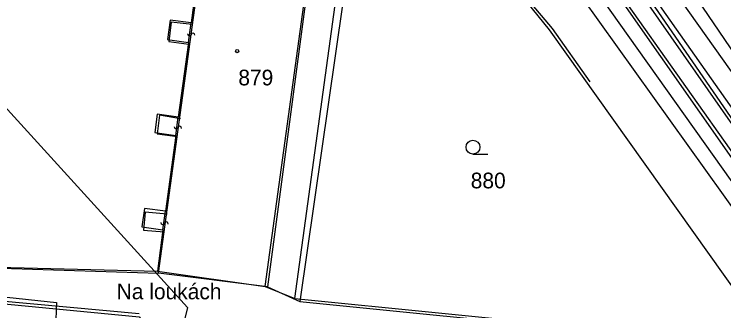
# Model space of a CAD drawing. Extents: x -469926 to -462499, y -1098642 to -1092733.
# Drawn here: x -465706.3 to -465629.3, y -1094774 to -1094741.9 of the extents above; entities that cross this region are included whole.
import ezdxf

# ---------------------------------------------------------------- set-up
doc = ezdxf.new("R2010")
doc.units = 0
for name, color, linetype in [('Vrstva 1', 7, 'Continuous'), ('Vrstva 10', 7, 'Continuous'), ('Vrstva 14', 7, 'Continuous'), ('Vrstva 16', 7, 'Continuous'), ('Vrstva 25', 7, 'Continuous'), ('Vrstva 4', 7, 'Continuous'), ('Vrstva 50', 7, 'Continuous'), ('Vrstva 6', 7, 'Continuous'), ('Vrstva 63', 7, 'Continuous')]:
    doc.layers.add(name, color=color, linetype=linetype)

msp = doc.modelspace()

# ---------------------------------------------------------------- linework, layer by layer
at = {"layer": 'Vrstva 1'}
for p, q in [((-465620.33, -1094764.94), (-465670.79, -1094691.66)), ((-465654.05, -1094726.95), (-465624.69, -1094768.01)), ((-465679.05, -1094771.4), (-465673.34, -1094729.79)), ((-465679.05, -1094771.4), (-465673.34, -1094729.79)), ((-465685.98, -1094734.61), (-465687.1, -1094742.81)), ((-465685.98, -1094734.61), (-465687.1, -1094742.81)), ((-465675.83, -1094772.71), (-465670.77, -1094735.7)), ((-465675.83, -1094772.71), (-465670.77, -1094735.7)), ((-465648.19, -1094743.56), (-465650.65, -1094740.51)), ((-465648.19, -1094743.56), (-465650.65, -1094740.51)), ((-465689.38, -1094742.5), (-465689.66, -1094744.62)), ((-465689.38, -1094742.5), (-465689.66, -1094744.62)), ((-465687.1, -1094742.81), (-465689.38, -1094742.5)), ((-465687.1, -1094742.81), (-465689.38, -1094742.5)), ((-465625.25, -1094775.81), (-465648.19, -1094743.56)), ((-465689.66, -1094744.62), (-465687.38, -1094744.93)), ((-465689.66, -1094744.62), (-465687.38, -1094744.93)), ((-465687.38, -1094744.93), (-465688.49, -1094753.03)), ((-465687.38, -1094744.93), (-465688.49, -1094753.03)), ((-465690.78, -1094752.71), (-465691.05, -1094754.72)), ((-465690.78, -1094752.71), (-465691.05, -1094754.72)), ((-465688.49, -1094753.03), (-465690.78, -1094752.71)), ((-465688.49, -1094753.03), (-465690.78, -1094752.71)), ((-465691.05, -1094754.72), (-465688.76, -1094755.03)), ((-465691.05, -1094754.72), (-465688.76, -1094755.03)), ((-465688.76, -1094755.03), (-465689.88, -1094763.24)), ((-465688.76, -1094755.03), (-465689.88, -1094763.24)), ((-465692.16, -1094762.93), (-465692.43, -1094764.94)), ((-465692.16, -1094762.93), (-465692.43, -1094764.94)), ((-465689.88, -1094763.24), (-465692.16, -1094762.93)), ((-465689.88, -1094763.24), (-465692.16, -1094762.93)), ((-465692.43, -1094764.94), (-465690.15, -1094765.25)), ((-465692.43, -1094764.94), (-465690.15, -1094765.25)), ((-465690.15, -1094765.25), (-465690.76, -1094769.73)), ((-465690.15, -1094765.25), (-465690.76, -1094769.73)), ((-465715.93, -1094769.1), (-465690.76, -1094769.73)), ((-465715.93, -1094769.1), (-465690.76, -1094769.73)), ((-465690.76, -1094769.73), (-465679.05, -1094771.4)), ((-465690.76, -1094769.73), (-465679.05, -1094771.4)), ((-465692.74, -1094774.39), (-465733.51, -1094770.57)), ((-465692.74, -1094774.39), (-465733.51, -1094770.57)), ((-465679.05, -1094771.4), (-465675.83, -1094772.71)), ((-465679.05, -1094771.4), (-465675.83, -1094772.71)), ((-465675.83, -1094772.71), (-465629.38, -1094777.32))]:
    msp.add_line(p, q, dxfattribs=at)
at = {"layer": 'Vrstva 10'}
msp.add_lwpolyline([(-465550.16, -1094876.62), (-465554.38, -1094868.04), (-465568.94, -1094847.26), (-465601.89, -1094798.03), (-465620.33, -1094764.94), (-465620.33, -1094764.94), (-465670.79, -1094691.66), (-465697.67, -1094652.61)], dxfattribs=at)
at = {"layer": 'Vrstva 14'}
for p, q in [((-465710.592, -1094748.288), (-465687.49, -1094773.704)), ((-465710.592, -1094748.288), (-465687.49, -1094773.704)), ((-465687.49, -1094773.704), (-465736.674, -1094971.797))]:
    msp.add_line(p, q, dxfattribs=at)
at = {"layer": 'Vrstva 16'}
for p, q in [((-465712.117, -1094772.008), (-465701.707, -1094773.143)), ((-465712.117, -1094772.008), (-465701.707, -1094773.143)), ((-465701.707, -1094773.143), (-465702.16, -1094784.266)), ((-465701.707, -1094773.143), (-465702.16, -1094784.266))]:
    msp.add_line(p, q, dxfattribs=at)
at = {"layer": 'Vrstva 25'}
msp.add_line((-465656.51, -1094757.04), (-465654.91, -1094757.04), dxfattribs=at)
msp.add_line((-465656.51, -1094757.04), (-465654.91, -1094757.04), dxfattribs=at)
for centre, radius in [((-465682.1, -1094745.87), 0.175), ((-465682.1, -1094745.87), 0.175), ((-465656.51, -1094756.29), 0.75), ((-465656.51, -1094756.29), 0.75)]:
    msp.add_circle(centre, radius, dxfattribs=at)
at = {"layer": 'Vrstva 4'}
for p, q in [((-465621.88, -1094766.03), (-465672.86, -1094693.84)), ((-465674.33, -1094695.38), (-465623.43, -1094767.12)), ((-465687.38, -1094744.93), (-465687.1, -1094742.81)), ((-465687.38, -1094744.93), (-465687.1, -1094742.81)), ((-465688.76, -1094755.03), (-465688.49, -1094753.03)), ((-465688.76, -1094755.03), (-465688.49, -1094753.03)), ((-465690.15, -1094765.25), (-465689.88, -1094763.24)), ((-465690.15, -1094765.25), (-465689.88, -1094763.24))]:
    msp.add_line(p, q, dxfattribs=at)
at = {"layer": 'Vrstva 6'}
msp.add_line((-465750.934, -1094581.981), (-465615.957, -1094775.392), dxfattribs=at)
for points in [[(-465759.83, -1094562.03), (-465724.66, -1094612.3), (-465708.74, -1094635.05), (-465698.93, -1094649.17), (-465687.13, -1094668.12), (-465674.06, -1094684.97), (-465656.74, -1094710.77), (-465644.72, -1094728.87), (-465624.87, -1094757.08), (-465617, -1094767.85), (-465608.19, -1094781.445)], [(-465434.36, -1095026.37), (-465448.49, -1095009.06), (-465466.41, -1094985.15), (-465481.4, -1094961.47), (-465496.39, -1094937.79), (-465514.47, -1094911.93), (-465541.255, -1094872.83), (-465568.04, -1094833.73), (-465581.135, -1094814.86), (-465597.23, -1094791.03), (-465612.74, -1094768.15), (-465622.568, -1094754.33), (-465641.197, -1094726.93), (-465652.461, -1094710.94), (-465670.86, -1094684.36), (-465683.59, -1094665.34), (-465705.04, -1094634.71), (-465721.42, -1094610.27), (-465739.86, -1094583.31), (-465754.366, -1094564.659), (-465741.97, -1094582.27)], [(-465601.1, -1094799.01), (-465619.15, -1094767.7), (-465625.621, -1094757.74), (-465636.356, -1094742.395), (-465646.95, -1094727.19), (-465657.996, -1094711.59), (-465677.28, -1094685.26), (-465689.046, -1094669.47), (-465702.48, -1094651.14), (-465710.3, -1094636.99), (-465726.9, -1094613.53), (-465741.385, -1094593.15), (-465755.87, -1094572.77)], [(-465741.97, -1094582.27), (-465721.96, -1094611.13), (-465705.49, -1094635.17), (-465696.21, -1094648.65), (-465684.35, -1094666.25), (-465671.36, -1094684.57), (-465662.225, -1094697.895), (-465653.09, -1094711.22), (-465642.9, -1094727.83), (-465633.03, -1094741.705), (-465623.16, -1094755.58), (-465614.39, -1094768.07), (-465597.56, -1094792.02), (-465581.68, -1094815.22), (-465569.22, -1094833.47), (-465562.56, -1094841.729)]]:
    msp.add_lwpolyline(points, dxfattribs=at)
at = {"layer": 'Vrstva 63'}
for p, q in [((-465687.073, -1094744.076), (-465687.073, -1094744.076)), ((-465687.073, -1094744.076), (-465687.073, -1094744.076)), ((-465688.52, -1094754.177), (-465688.52, -1094754.177)), ((-465688.52, -1094754.177), (-465688.52, -1094754.177)), ((-465689.967, -1094764.558), (-465689.967, -1094764.558)), ((-465689.967, -1094764.558), (-465689.967, -1094764.558))]:
    msp.add_line(p, q, dxfattribs=at)
for points in [[(-465715.734, -1094769.184), (-465690.638, -1094769.958), (-465684.695, -1094726.619), (-465675.26, -1094727.872), (-465675.524, -1094729.831), (-465673.27, -1094729.883), (-465678.795, -1094771.462), (-465690.638, -1094769.958)], [(-465715.734, -1094769.184), (-465690.638, -1094769.958), (-465684.695, -1094726.619), (-465675.26, -1094727.872), (-465675.524, -1094729.831), (-465673.27, -1094729.883), (-465678.795, -1094771.462), (-465690.638, -1094769.958)], [(-465643.795, -1094749.199), (-465647.884, -1094743.421), (-465650.495, -1094740.321), (-465655.741, -1094735.574), (-465658.838, -1094733.286), (-465669.864, -1094735.27), (-465675.311, -1094773.041)], [(-465643.795, -1094749.199), (-465647.884, -1094743.421), (-465650.495, -1094740.321), (-465655.741, -1094735.574), (-465658.838, -1094733.286), (-465669.864, -1094735.27), (-465675.311, -1094773.041)], [(-465686.99, -1094742.991), (-465689.248, -1094742.738), (-465689.509, -1094744.847), (-465687.351, -1094745.102)], [(-465686.99, -1094742.991), (-465689.248, -1094742.738), (-465689.509, -1094744.847), (-465687.351, -1094745.102)], [(-465686.704, -1094744.15), (-465686.734, -1094743.994), (-465686.879, -1094743.912), (-465687.021, -1094743.966), (-465687.139, -1094744.193), (-465687.288, -1094744.235), (-465687.421, -1094744.148), (-465687.441, -1094744.001)], [(-465686.704, -1094744.15), (-465686.734, -1094743.994), (-465686.879, -1094743.912), (-465687.021, -1094743.966), (-465687.139, -1094744.193), (-465687.288, -1094744.235), (-465687.421, -1094744.148), (-465687.441, -1094744.001)], [(-465688.25, -1094753.233), (-465690.51, -1094752.83), (-465690.773, -1094754.839), (-465688.564, -1094755.143)], [(-465688.25, -1094753.233), (-465690.51, -1094752.83), (-465690.773, -1094754.839), (-465688.564, -1094755.143)], [(-465688.151, -1094754.251), (-465688.181, -1094754.095), (-465688.326, -1094754.013), (-465688.468, -1094754.067), (-465688.586, -1094754.294), (-465688.735, -1094754.336), (-465688.868, -1094754.249), (-465688.888, -1094754.102)], [(-465688.151, -1094754.251), (-465688.181, -1094754.095), (-465688.326, -1094754.013), (-465688.468, -1094754.067), (-465688.586, -1094754.294), (-465688.735, -1094754.336), (-465688.868, -1094754.249), (-465688.888, -1094754.102)], [(-465689.707, -1094763.579), (-465692.078, -1094763.33), (-465692.278, -1094765.286), (-465690.021, -1094765.489)], [(-465689.707, -1094763.579), (-465692.078, -1094763.33), (-465692.278, -1094765.286), (-465690.021, -1094765.489)], [(-465689.598, -1094764.632), (-465689.628, -1094764.476), (-465689.773, -1094764.394), (-465689.915, -1094764.448), (-465690.033, -1094764.675), (-465690.182, -1094764.717), (-465690.315, -1094764.63), (-465690.335, -1094764.483)], [(-465689.598, -1094764.632), (-465689.628, -1094764.476), (-465689.773, -1094764.394), (-465689.915, -1094764.448), (-465690.033, -1094764.675), (-465690.182, -1094764.717), (-465690.315, -1094764.63), (-465690.335, -1094764.483)], [(-465733.275, -1094770.805), (-465692.751, -1094774.71), (-465673.295, -1094800.34), (-465652.159, -1094843.41), (-465643.795, -1094853.605)], [(-465678.795, -1094771.462), (-465675.311, -1094773.041), (-465643.795, -1094776.2)]]:
    msp.add_lwpolyline(points, dxfattribs=at)

# ---------------------------------------------------------------- texts
at = {"layer": 'Vrstva 50'}
for s, p in [('879', (-465681.971, -1094749.59)), ('880', (-465656.752, -1094760.76)), ('Na loukách', (-465695.173, -1094772.8)), ('Na loukách', (-465695.173, -1094772.8))]:
    msp.add_text(s, height=1.7, dxfattribs=at).set_placement(p)

doc.saveas('drawing.dxf')
